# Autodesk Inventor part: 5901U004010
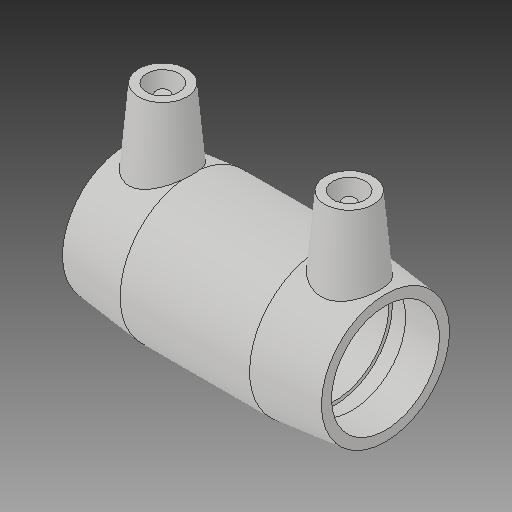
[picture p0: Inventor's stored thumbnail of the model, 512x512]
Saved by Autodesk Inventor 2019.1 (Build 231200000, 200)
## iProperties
Created: 2017-06
Part Number: 5901U004010
Material: Generic
Description: PLASSON CTS COUPLER 1''
Document SubType Name: Modeling
Designer: KIM
Mass: 72.9589 g
Surface Area: 285.531 cm^2
Volume: 72.9589 cm^3
Density: 1 g/cm^3
Appearance: Default
Author: KIM
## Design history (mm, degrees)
derived "5901U.ipt"
feature "Solid1::5901U.ipt"
tag "TaggingFeature1"
body "Solid1"
other parameters: "d0" = 80.01, "d1" = 33.3, "d2" = 43.942, "d3" = 39.116, "d4" = 20.0025, "d5" = 39.5478, "d6" = 26.64, "d7" = 33.3, "d8" = 168 deg, "d10" = 15.6464, "d11" = 5.21547, "d29" = 41.91, "d30" = 15, "d31" = 28.8036, "d34" = 5 deg, "d41" = 4, "d42" = 14, "d43" = 0, "d48" = 3, "d49" = 0, "d_" = 33.3, "L_" = 80.01, "L_1" = 39.116, "D_" = 43.942, "A_" = 41.91, "d_2" = 12
